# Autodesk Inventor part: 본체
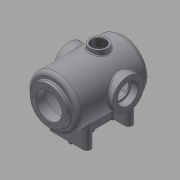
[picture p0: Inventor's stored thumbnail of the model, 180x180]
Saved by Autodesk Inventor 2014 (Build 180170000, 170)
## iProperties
Created: 2016-02
Part Number: 본체
Material: Aluminum 6061
Document SubType Name: Modeling
Designer: mduedu
Density: 2.71 g/cm^3
Appearance: Default
Author: mduedu
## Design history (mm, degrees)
sketch "스케치2"
  geometry: L1 (0, 100)-(0, -100); L2 (65, -75.993)-(65, 100); L3 (65, 100)-(0, 100); A1 r 100 centre (0, 0) between (0, -100) and (65, -75.993); 2 further points
  constraints: 6 end point, 2 midpoint, 2 point on circle, 1 centre point, 1 coincident, 1 horizontal, 1 parallel, 1 vertical
  dimensions: "d3" = 200 distance of L1.start L1.end; "d5" = 130 diameter of L2 L1; "d6" = 100 radius of A1
revolve "회전1" sketch "스케치2" stored, may be unused: angle "d7" = 90 deg
sketch "스케치3"
  geometry: C1 r 47.5 at (0, 0); 1 further point
  constraints: 1 centre point, 1 coincident
  dimensions: "d8" = 95 diameter of C1
extrude "돌출2" join sketch "스케치3" distance "d10" = 10; taper "d11" = 0 deg
sketch "스케치5"
  geometry: L1 (47.5, 110)-(47.5, 100) reference; L2 (47.5, 100)-(65, 100) reference; L3 (65, 100)-(65, -75.993) reference; L4 (-65, -75.993)-(-65, 100) reference; L5 (-65, 100)-(-47.5, 100) reference; L6 (-47.5, 100)-(-47.5, 110) reference; L7 (-47.5, 110)-(47.5, 110) reference; L8 (55, 85)-(55, -71.239); L9 (0, 85)-(55, 85); L10 (0, 85)-(0, -90); A1 r 100 centre (0, 0) between (0, -100) and (65, -75.993) reference; A2 r 100 centre (0, 0) between (-65, -75.993) and (0, -100) reference; A3 r 90 centre (0, 0) between (0, -90) and (55, -71.239); 1 further point
  constraints: 6 end point, 2 point on circle, 1 centre point, 1 parallel, 1 perpendicular, 1 point on line, 1 vertical
  dimensions: "d13" = 10 distance between parallel lines of L3 L8; "d14" = 10 radial gap between concentric circles of A3 A1; "d15" = 15 distance between parallel lines of L9 L2
revolve "회전2" sketch "스케치5" stored, may be unused: angle "d16" = 90 deg
hole "구멍1" diameter "d19" = 65; stored, may be unused: countersink angle "d23" = 90 deg, drill point angle "d25" = 118 deg; dims "d17" = 10, "d18" = 10, "d20" = 6, "d21" = 4, "d22" = 2, "d24" = 8
node "작업 평면1"
sketch "스케치6"
  geometry: L1 (47.5, 110)-(-47.5, 110) reference; C1 r 40 at (0, -17); 1 further point
  constraints: 1 centre point, 1 vertical alignment
  dimensions: "d27" = 80 diameter of C1; "d29" = 127 distance from line of C1.centre L1
extrude "돌출3" join sketch "스케치6" stored distance "d30" = 10; taper "d31" = 0 deg
hole "구멍2" diameter "d34" = 42; stored, may be unused: countersink angle "d38" = 90 deg, drill point angle "d40" = 118 deg; dims "d32" = 10, "d33" = 10, "d35" = 6, "d36" = 52, "d37" = 18, "d39" = 8
sketch "스케치7" dims "d41" = 65
  geometry: C1 r 40 at (0, 0) reference; 3 further points
  constraints: 2 vertical alignment, 1 coincident, 2 other
hole "구멍3" sketch "스케치7" at (0, 32.5) diameter "d43" = 3.242; stored, may be unused: countersink angle "d47" = 90 deg, drill point angle "d49" = 118 deg; dims "d44" = 11, "d45" = 13, "d46" = 18, "d48" = 13
sketch "스케치8" dims "d53" = 80
  geometry: 3 further points
  constraints: 2 vertical alignment, 1 coincident, 2 other
hole "구멍4" sketch "스케치8" at (0, 40) diameter "d56" = 3.242; stored, may be unused: countersink angle "d60" = 90 deg, drill point angle "d62" = 118 deg; dims "d57" = 11, "d58" = 13, "d59" = 18, "d61" = 13
fillet "모깎기1" dims "d66" = 10
fillet "모깎기2" dims "d67" = 3
fillet "모깎기3" dims "d68" = 0.3
chamfer "모따기1" distance "d69" = 1; stored, may be unused: second distance "d70" = 2, angle "d71" = 45 deg
node "작업 평면5"
sketch "스케치10"
  geometry: L1 (-50, -63)-(50, -63); L2 (50, -63)-(50, -43); L3 (50, -43)-(-50, -43); L4 (-50, -43)-(-50, -63); L5 (-50, 0)-(50, 0); L6 (-50, 63)-(50, 63); L7 (50, 63)-(50, 43); L8 (50, 43)-(-50, 43); L9 (-50, 43)-(-50, 63); 2 further points
  constraints: 18 end point, 4 symmetric about line, 2 parallel, 2 perpendicular, 1 coincident, 1 horizontal, 1 midpoint
  dimensions: "d80" = 20 distance of L3.end L1.start; "d82" = 100 distance of L1.start L1.end; "d130" = 43 vertical distance of L3.end point (0, 0); "d131" = 50 horizontal distance of L3.end point (0, 0); "d132" = 100 distance of L5.start L5.end
extrude "돌출5" join sketch "스케치10" stored distance "d84" = 10; taper "d85" = 0 deg
sketch "스케치11"
  geometry: L1 (-100, -43)-(-100, 43); L2 (-65, 90)-(-65, -71.239) reference; L3 (-100, -43)-(-41.533, -43) reference; L4 (-100, 43)-(-41.533, 43) reference; 1 further point
  constraints: 2 end point, 1 point on line, 1 vertical
feature "리브1" sketch "스케치11" dims "d88" = 1, "d89" = 20, "d90" = 0, "d91" = 0, "d92" = 1, "d93" = 1
fillet "모깎기12"
fillet "모깎기13"
fillet "모깎기14"
fillet "모깎기15"
fillet "모깎기16" dims "d167" = 3
fillet "모깎기17" dims "d168" = 3
node "작업 평면6"
sketch "스케치19"
  geometry: L1 (75, -57)-(75, 23) reference; L2 (-75, -57)-(-75, 23) reference; L3 (75, -17)-(-75, -17); C1 r 22.5 at (0, -17); 1 further point
  constraints: 3 midpoint, 2 end point, 1 centre point
  dimensions: "d149" = 45 diameter of C1
extrude "돌출11" join sketch "스케치19" stored distance "d150" = 10; taper "d151" = 0 deg
hole "구멍6" diameter "d154" = 35; stored, may be unused: countersink angle "d158" = 90 deg, drill point angle "d160" = 118 deg; dims "d152" = 10, "d153" = 10, "d155" = 6, "d156" = 4, "d157" = 2, "d159" = 8
fillet "모깎기11" dims "d161" = 3
feature "스레드1" dims "d162" = 10, "d163" = 0
chamfer "모따기3" distance "d164" = 1; stored, may be unused: second distance "d165" = 2, angle "d166" = 45 deg
sketch "스케치20"
  geometry: L1 (10, 40)-(10, -40) reference; L2 (13, -43)-(40, -43) reference; L3 (40, -63)-(-40, -63) reference; L4 (-40, -43)-(-13, -43) reference; L5 (-10, -40)-(-10, 40) reference; L6 (-13, 43)-(-40, 43) reference; L7 (-40, 63)-(40, 63) reference; L8 (40, 43)-(13, 43) reference; L9 (-40, 53)-(40, 53); L10 (-40, -53)-(40, -53); L11 (0, 53)-(0, -53); C1 r 5 at (0, 53); C2 r 5 at (0, 0); C3 r 5 at (0, -53); A1 r 3 centre (13, -40) between (10, -40) and (13, -43) reference; A2 r 10 centre (40, -53) between (40, -63) and (40, -43) reference; A3 r 10 centre (-40, -53) between (-40, -43) and (-40, -63) reference; A4 r 3 centre (-13, -40) between (-13, -43) and (-10, -40) reference; A5 r 3 centre (-13, 40) between (-10, 40) and (-13, 43) reference; A6 r 10 centre (-40, 53) between (-40, 63) and (-40, 43) reference; A7 r 10 centre (40, 53) between (40, 43) and (40, 63) reference; A8 r 3 centre (13, 40) between (13, 43) and (10, 40) reference; 1 further point
  constraints: 6 end point, 3 centre point, 3 coincident, 2 midpoint, 2 parallel
  dimensions: "d169" = 10 diameter of C1; "d170" = 10 diameter of C2; "d171" = 10 diameter of C3
extrude "돌출12" join sketch "스케치20" distance "d172" = 10; taper "d173" = 0 deg
chamfer "모따기4" distance "d174" = 1; stored, may be unused: second distance "d175" = 2, angle "d176" = 45 deg
node "솔리드2"
pattern_circular "원형 패턴1" dims angle "d51" = 360 deg
mirror "대칭1"
pattern_circular "원형 패턴2" dims angle "d64" = 360 deg
node "절단 모서리 투영1"
node "절단 모서리 투영4"
other parameters: "d26" = 75, "d136" = 175
